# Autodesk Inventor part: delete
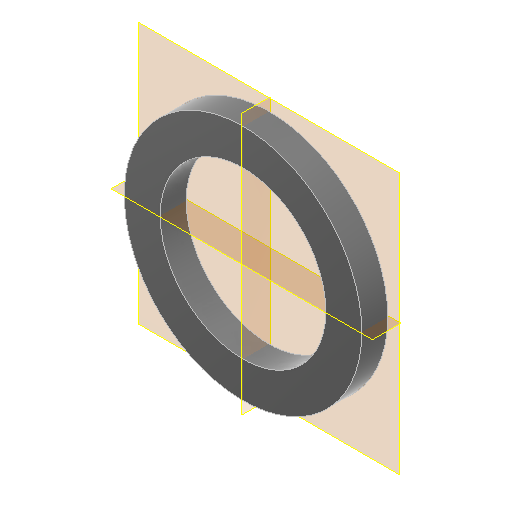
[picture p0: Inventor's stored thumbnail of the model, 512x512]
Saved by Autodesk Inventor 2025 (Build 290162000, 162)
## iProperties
Created: 2025-03
Part Number: delete
Material: Thermoplastic Resin
Document SubType Name: Modeling
Designer: dansp
Density: 1.28 g/cm^3
Appearance: Smooth - Black
Mass: 31.6673 g
Surface Area: 94.5619 cm^2
Volume: 24.74 cm^3
Author: dansp
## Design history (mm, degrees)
sketch "Sketch1"
  geometry: L1 (0, 57.75)-(0, -57.75) reference; L2 (-57.75, 0)-(57.75, 0) reference; C1 r 41.25 at (0, 0); C2 r 28.75 at (0, 0); 1 further point
  constraints: 2 centre point, 2 coincident
  dimensions: "d0" = 82.5 diameter of C1; "d1" = 12.5 radial gap between concentric circles of C1 C2
extrude "Extrusion1" new body sketch "Sketch1" distance "d2" = 9; taper "d3" = 0 deg
body "Solid1"
